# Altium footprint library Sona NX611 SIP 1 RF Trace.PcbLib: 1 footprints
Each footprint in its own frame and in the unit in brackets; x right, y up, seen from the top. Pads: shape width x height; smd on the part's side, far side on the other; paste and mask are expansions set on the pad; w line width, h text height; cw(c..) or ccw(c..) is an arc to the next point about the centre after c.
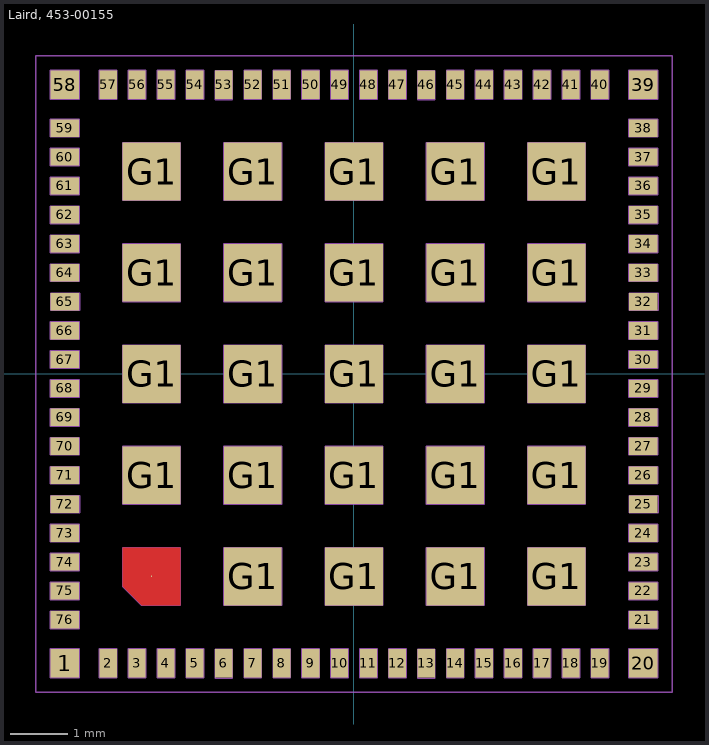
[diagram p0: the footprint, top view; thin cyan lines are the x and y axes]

## Laird, 453-00155 [mm] "Laird Sona NX611 SIP"
pads (101):
  rect 0.5x0.5 smd mask+0.051: 1(-5,-5) 20(5,-5) 39(5,5) 58(-5,5)
  rect 0.3x0.5 smd mask+0.051: 2(-4.25,-5) 3(-3.75,-5) 4(-3.25,-5) 5(-2.75,-5) 6(-2.25,-5) 7(-1.75,-5) 8(-1.25,-5) 9(-0.75,-5) 10(-0.25,-5) 11(0.25,-5) 12(0.75,-5) 13(1.25,-5) 14(1.75,-5) 15(2.25,-5) 16(2.75,-5) 17(3.25,-5) 18(3.75,-5) 19(4.25,-5) 40(4.25,5) 41(3.75,5) 42(3.25,5) 43(2.75,5) 44(2.25,5) 45(1.75,5) 46(1.25,5) 47(0.75,5) 48(0.25,5) 49(-0.25,5) 50(-0.75,5) 51(-1.25,5) 52(-1.75,5) 53(-2.25,5) 54(-2.75,5) 55(-3.25,5) 56(-3.75,5) 57(-4.25,5)
  rect 0.5x0.3 smd mask+0.051: 21(5,-4.25) 22(5,-3.75) 23(5,-3.25) 24(5,-2.75) 25(5,-2.25) 26(5,-1.75) 27(5,-1.25) 28(5,-0.75) 29(5,-0.25) 30(5,0.25) 31(5,0.75) 32(5,1.25) 33(5,1.75) 34(5,2.25) 35(5,2.75) 36(5,3.25) 37(5,3.75) 38(5,4.25) 59(-5,4.25) 60(-5,3.75) 61(-5,3.25) 62(-5,2.75) 63(-5,2.25) 64(-5,1.75) 65(-5,1.25) 66(-5,0.75) 67(-5,0.25) 68(-5,-0.25) 69(-5,-0.75) 70(-5,-1.25) 71(-5,-1.75) 72(-5,-2.25) 73(-5,-2.75) 74(-5,-3.25) 75(-5,-3.75) 76(-5,-4.25)
  round 0.025 smd mask+0.051: G1(-3.5,-3.5)
  rect 1x1 smd mask+0.051: G1(-3.5,-1.75) G1(-3.5,0) G1(-3.5,1.75) G1(-3.5,3.5) G1(-1.75,-3.5) G1(-1.75,-1.75) G1(-1.75,0) G1(-1.75,1.75) G1(-1.75,3.5) G1(0,-3.5) G1(0,-1.75) G1(0,0) G1(0,1.75) G1(0,3.5) G1(1.75,-3.5) G1(1.75,-1.75) G1(1.75,0) G1(1.75,1.75) G1(1.75,3.5) G1(3.5,-3.5) G1(3.5,-1.75) G1(3.5,0) G1(3.5,1.75) G1(3.5,3.5)
Top Layer:
  region: -3,-4 -3.671,-4 -4,-3.67 -4,-3 -3,-3
Top Assembly (Mech13):
  drawing of 409 lines, arcs and shapes, not listed
  text ".designator" at -1.123,0.55 h1.27
3D body "Sona_NX611_SIP.STEP": height 1.7, standoff 0.03, extent -5.503,-5.5 5.497,5.5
